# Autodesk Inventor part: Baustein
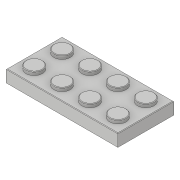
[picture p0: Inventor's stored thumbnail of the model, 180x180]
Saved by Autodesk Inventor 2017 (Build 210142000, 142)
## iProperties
Created: 2016-09
Part Number: Baustein
Material: Generic
Document SubType Name: Modeling
Designer: e_krauts
Density: 1 g/cm^3
Appearance: Default
Author: e_krauts
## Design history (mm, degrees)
sketch "Skizze1"
  geometry: L1 (-32, 16)-(32, 16); L2 (32, 16)-(32, -16); L3 (32, -16)-(-32, -16); L4 (-32, -16)-(-32, 16); L5 (0, 16)-(0, -16); L6 (-32, 0)-(32, 0); C1 r 4.7 at (-8, 8); C2 r 4.7 at (-24, 8); C3 r 4.7 at (8, 8); C4 r 4.7 at (24, 8); C5 r 4.7 at (-8, -8); C6 r 4.7 at (-24, -8); C7 r 4.7 at (8, -8); C8 r 4.7 at (24, -8); 1 further point
  constraints: 12 end point, 8 centre point, 6 midpoint, 6 symmetric about line, 2 parallel, 1 horizontal, 1 perpendicular, 6 other
  dimensions: "d0" = 64 distance of L2.end L3.end; "d1" = 32 distance of L1.end L2.end; "d2" = 9.4 diameter of C1; "d3" = 9.4 diameter of C2; "d4" = 16 diameter of C1.centre L5; "d5" = 48 diameter of C2.centre L5; "d19" = 16 diameter of C3.centre L6; "d20" = 16 diameter of C4.centre L6
extrude "Extrusion1" new body sketch "Skizze1" distance "d6" = 7; taper "d7" = 0 deg
extrude "Extrusion2" join sketch "Skizze1" distance "d8" = 2; taper "d9" = 0 deg
chamfer "Fase1" distance "d10" = 0.3; stored, may be unused: second distance "d11" = 2, angle "d12" = 45 deg
sketch "Skizze2" dims "d24" = 10, "d31" = 10
  geometry: L1 (32, 16)-(-32, 16) reference; L2 (0, 16)-(0, -16); L3 (-32, -16)-(32, -16) reference; L4 (32, -16)-(32, 16) reference; L5 (32, 0)-(-32, 0); L6 (-32, -16)-(-32, 16) reference; L7 (-0.036, 1.377)-(0, 1.413); L8 (2.828, 4.242)-(4.046, 5.459); L9 (1.322, -0.092)-(1.413, 0); L10 (4.242, 2.828)-(5.459, 4.046); L11 (-2.828, 4.242)-(-4.046, 5.459); L12 (-4.242, 2.828)-(-5.459, 4.046); L13 (-2.828, -4.242)-(-4.046, -5.459); L14 (-4.242, -2.828)-(-5.459, -4.046); L15 (-0.036, -1.377)-(0, -1.413); L16 (2.828, -4.242)-(4.046, -5.459); L17 (4.242, -2.828)-(5.459, -4.046); L18 (-13.172, -4.242)-(-11.954, -5.459); L19 (-11.758, -2.828)-(-10.541, -4.046); L20 (-13.172, 4.242)-(-11.954, 5.459); L21 (-18.828, 4.242)-(-20.046, 5.459); L22 (-20.242, 2.828)-(-21.459, 4.046); L23 (-20.242, -2.828)-(-21.459, -4.046); L24 (-18.828, -4.242)-(-20.046, -5.459); L25 (-11.758, 2.828)-(-10.541, 4.046); L26 (18.828, -4.242)-(20.046, -5.459); L27 (20.242, 2.828)-(21.459, 4.046); L28 (18.828, 4.242)-(20.046, 5.459); L29 (20.242, -2.828)-(21.459, -4.046); L30 (13.172, -4.242)-(11.954, -5.459); L31 (11.758, -2.828)-(10.541, -4.046); L32 (11.758, 2.828)-(10.541, 4.046); L33 (13.172, 4.242)-(11.954, 5.459); A1 r 4 centre (7.07, 0) between (4.242, 2.828) and (3.07, 0); A2 r 4 centre (0, 7.07) between (0, 3.07) and (2.828, 4.242); A3 r 4.7 centre (8, 8) between (4.046, 5.459) and (5.459, 4.046); A4 r 4.7 centre (-8, 8) between (-5.459, 4.046) and (-4.046, 5.459); A5 r 4 centre (0, 7.07) between (-2.828, 4.242) and (0, 3.07); A6 r 4 centre (-7.07, 0) between (-3.07, 0) and (-4.242, 2.828); A7 r 4 centre (0, -7.07) between (0, -3.07) and (-2.828, -4.242); A8 r 4 centre (-7.07, 0) between (-4.242, -2.828) and (-3.07, 0); A9 r 4.7 centre (-8, -8) between (-4.046, -5.459) and (-5.459, -4.046); A10 r 4 centre (0, -7.07) between (2.828, -4.242) and (0, -3.07); A11 r 4 centre (7.07, 0) between (3.07, 0) and (4.242, -2.828); A12 r 4.7 centre (8, -8) between (5.459, -4.046) and (4.046, -5.459); A13 r 4 centre (-16, -7.07) between (-13.172, -4.242) and (-16, -3.07); A14 r 4.7 centre (-8, -8) between (-10.541, -4.046) and (-11.954, -5.459); A15 r 4 centre (-8.93, 0) between (-12.93, 0) and (-11.758, -2.828); A16 r 4 centre (-8.93, 0) between (-11.758, 2.828) and (-12.93, 0); A17 r 4.7 centre (-8, 8) between (-11.954, 5.459) and (-10.541, 4.046); A18 r 4 centre (-16, 7.07) between (-16, 3.07) and (-13.172, 4.242); A19 r 4 centre (-16, 7.07) between (-18.828, 4.242) and (-16, 3.07); A20 r 4.7 centre (-24, 8) between (-21.459, 4.046) and (-20.046, 5.459); A21 r 4 centre (-23.07, 0) between (-19.07, 0) and (-20.242, 2.828); A22 r 4 centre (-23.07, 0) between (-20.242, -2.828) and (-19.07, 0); A23 r 4.7 centre (-24, -8) between (-20.046, -5.459) and (-21.459, -4.046); A24 r 4 centre (-16, -7.07) between (-16, -3.07) and (-18.828, -4.242); A25 r 4.7 centre (24, 8) between (20.046, 5.459) and (21.459, 4.046); A26 r 4.7 centre (24, -8) between (21.459, -4.046) and (20.046, -5.459); A27 r 4 centre (23.07, 0) between (19.07, 0) and (20.242, -2.828); A28 r 4 centre (16, -7.07) between (18.828, -4.242) and (16, -3.07); A29 r 4 centre (23.07, 0) between (20.242, 2.828) and (19.07, 0); A30 r 4 centre (16, 7.07) between (16, 3.07) and (18.828, 4.242); A31 r 4 centre (16, -7.07) between (16, -3.07) and (13.172, -4.242); A32 r 4.7 centre (8, -8) between (11.954, -5.459) and (10.541, -4.046); A33 r 4 centre (8.93, 0) between (11.758, -2.828) and (12.93, 0); A34 r 4 centre (8.93, 0) between (12.93, 0) and (11.758, 2.828); A35 r 4 centre (16, 7.07) between (13.172, 4.242) and (16, 3.07); A36 r 4.7 centre (8, 8) between (10.541, 4.046) and (11.954, 5.459); A37 r 3 centre (28, 12) between (28.58, 9.057) and (25.057, 12.58); A38 r 3 centre (-28, 12) between (-25.057, 12.58) and (-28.58, 9.057); A39 r 3 centre (-28, -12) between (-28.58, -9.057) and (-25.057, -12.58); A40 r 3 centre (28, -12) between (25.057, -12.58) and (28.58, -9.057); A41 r 12.5 centre (-16, 2.6) between (-8.585, 12.663) and (-23.415, 12.663); A42 r 12.5 centre (0, 2.6) between (7.415, 12.663) and (-7.415, 12.663); A43 r 12.5 centre (16, 2.6) between (23.415, 12.663) and (8.585, 12.663); A44 r 12.5 centre (16, 2.6) between (5.338, -3.925) and (5.427, -4.067); A45 r 12.5 centre (-18.5, 0) between (-28.647, 7.299) and (-28.647, -7.299); A46 r 12.5 centre (18.5, 0) between (28.647, -7.299) and (28.647, 7.299); A47 r 12.5 centre (-16, -2.6) between (-23.415, -12.663) and (-8.585, -12.663); A48 r 12.5 centre (0, -2.6) between (-7.415, -12.663) and (7.415, -12.663); A49 r 12.5 centre (16, -2.6) between (8.585, -12.663) and (23.415, -12.663); A50 r 4.7 centre (-24, 8) between (-23.415, 12.663) and (-25.057, 12.58); A51 r 4.7 centre (-24, 8) between (-28.58, 9.057) and (-28.647, 7.299); A52 r 4.7 centre (-24, -8) between (-28.647, -7.299) and (-28.58, -9.057); A53 r 4.7 centre (-24, -8) between (-25.057, -12.58) and (-23.415, -12.663); A54 r 4.7 centre (-8, -8) between (-8.585, -12.663) and (-7.415, -12.663); A55 r 4.7 centre (8, -8) between (7.415, -12.663) and (8.585, -12.663); A56 r 4.7 centre (24, -8) between (23.415, -12.663) and (25.057, -12.58); A57 r 4.7 centre (24, -8) between (28.58, -9.057) and (28.647, -7.299); A58 r 4.7 centre (24, 8) between (28.647, 7.299) and (28.58, 9.057); A59 r 4.7 centre (24, 8) between (25.057, 12.58) and (23.415, 12.663); A60 r 4.7 centre (8, 8) between (8.585, 12.663) and (7.415, 12.663); A61 r 4.7 centre (-8, 8) between (-7.415, 12.663) and (-8.585, 12.663); 10 further points
  constraints: 123 point on circle, 61 centre point, 58 end point, 36 symmetric about line, 9 point on line, 4 midpoint, 4 tangent, 2 horizontal, 1 coincident, 112 other
  dimensions: "d27" = 16 distance of A7.centre A13.centre; "d34" = 16 distance of A3.centre A25.centre; "d37" = 56 diameter of A37.centre L2
extrude "Extrusion3" cut sketch "Skizze2" distance "d47" = 2.5; taper "d48" = 0 deg
chamfer "Fase2" distance "d49" = 0.3; stored, may be unused: second distance "d50" = 2, angle "d51" = 45 deg
node "Volumenkörper1"
other parameters: "d21" = 45 deg, "d39" = 25, "d41" = 25, "d42" = 25
